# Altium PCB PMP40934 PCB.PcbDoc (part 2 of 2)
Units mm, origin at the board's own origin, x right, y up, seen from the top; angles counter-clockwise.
Board outline 30.1 x 65.43 mm, 4 copper layers (Component Side, Signal Layer 1, Signal Layer 2, Solder Side), stack 0.921 mm thick; 71 components, 34 nets, 202 pads, 421 vias.
Unrouted connection lines stored in the file: 46.
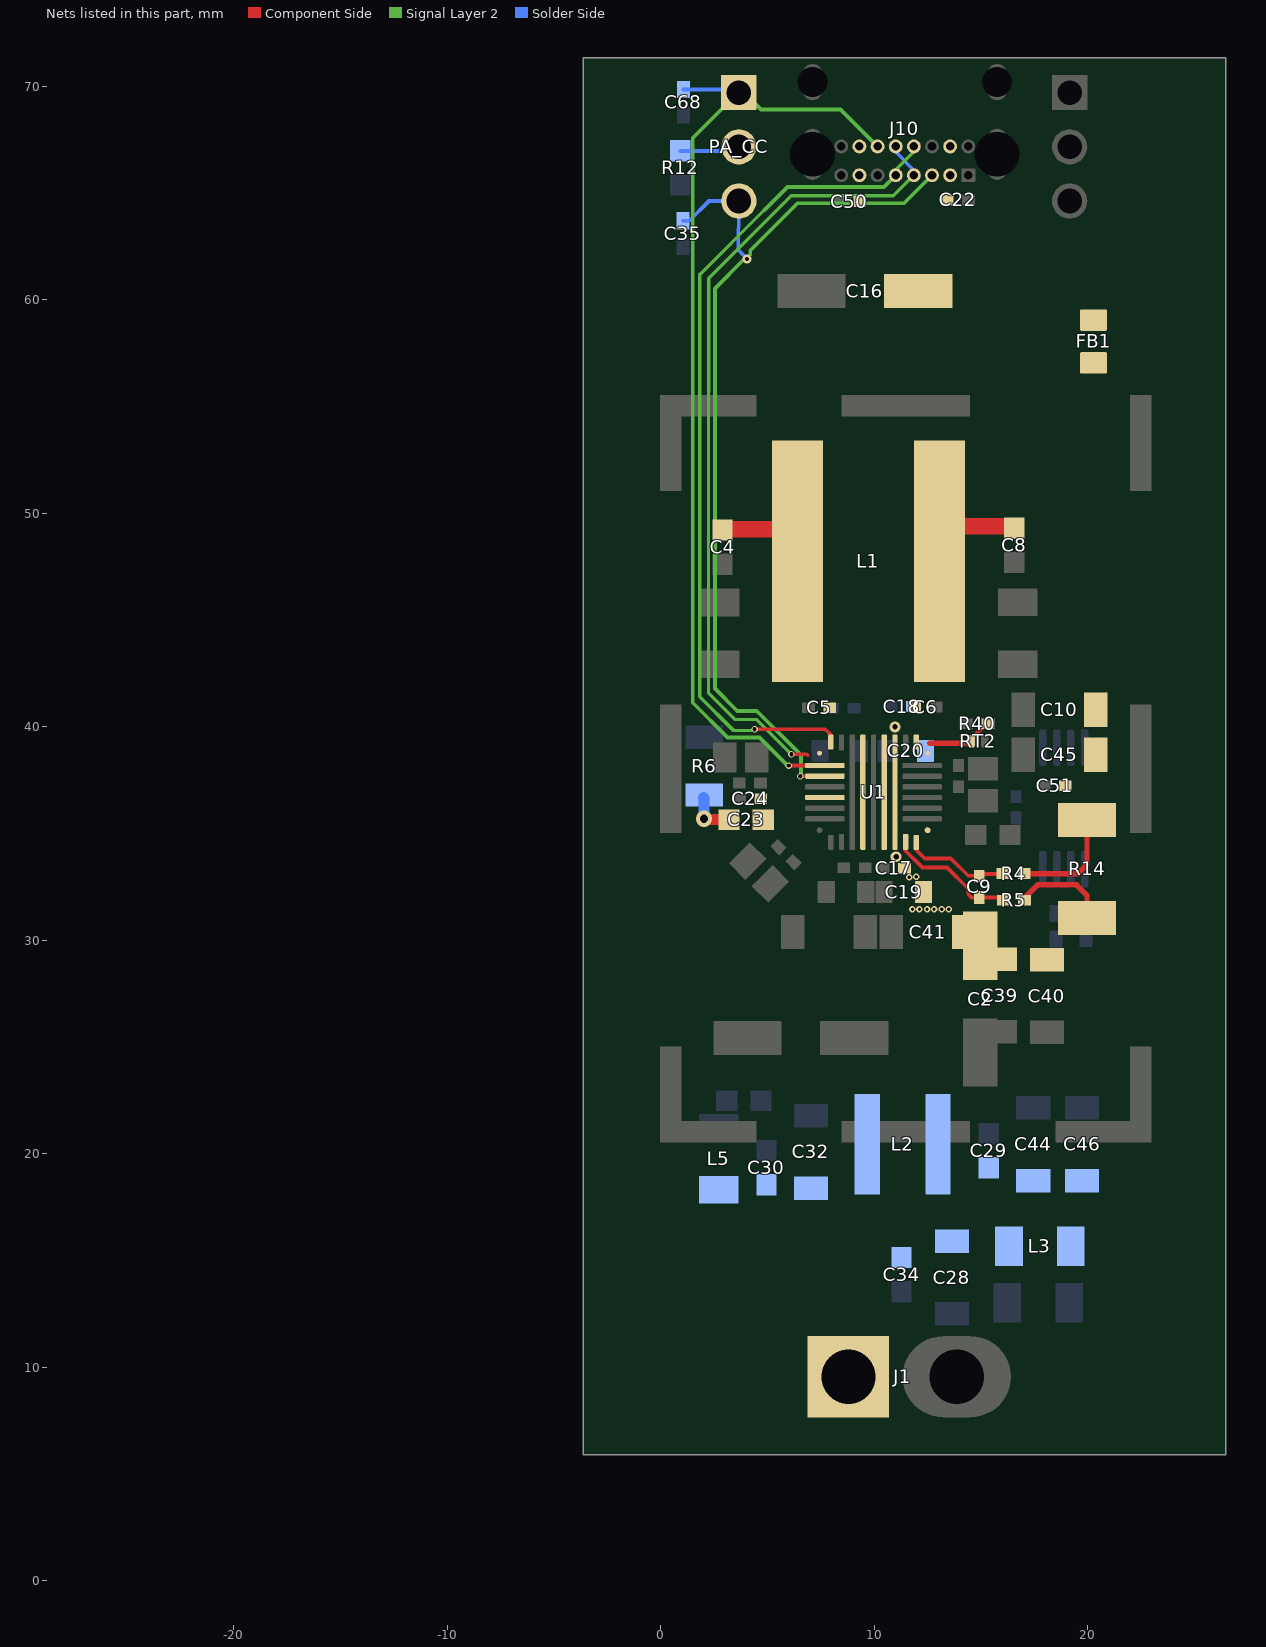
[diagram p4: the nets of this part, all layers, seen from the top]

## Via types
v1: diameter 0.762, hole 0.381, Component Side to Solder Side, 234 vias
v2: diameter 0.305, hole 0.152, Component Side to Solder Side, 135 vias
v3: diameter 0.305, hole 0.203, Component Side to Solder Side, 21 vias
v4: diameter 0.406, hole 0.203, Component Side to Solder Side, 10 vias
v5: diameter 0.381, hole 0.254, Component Side to Solder Side, tented both sides, 9 vias
v6: diameter 0.635, hole 0.381, Component Side to Solder Side, 7 vias
v7: diameter 0.508, hole 0.254, Component Side to Solder Side, 3 vias
v8: diameter 0.508/0.508/0.508/0.508 (per signal layer), hole 0.254, Component Side to Solder Side, 1 vias
v9: diameter 0.406, hole 0.254, Component Side to Solder Side, 1 vias

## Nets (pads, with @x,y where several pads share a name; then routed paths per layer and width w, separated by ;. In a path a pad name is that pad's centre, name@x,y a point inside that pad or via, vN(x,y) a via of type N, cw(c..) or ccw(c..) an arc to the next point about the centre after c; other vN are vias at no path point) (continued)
NetC9_1: C9.1 R5.1 U1.28 | length 6
  Component Side w0.178: U1.28@11.468,34.607 11.468,34.193 12.26,33.401 13.411,33.401 14.402,32.41 14.402,32.156 14.554,32.004 14.859,32.004 C9.1@14.884,31.979 ; C9.1@14.91,31.995 15.859,31.995 R5.1@16.002,31.852
NetC9_2: C9.2 R4.1 U1.29 | length 4.9
  Component Side w0.178: U1.29@11.968,34.582 11.968,34.227 12.363,33.833 13.586,33.833 14.398,33.02 C9.2@14.859,33.02 ; C9.2@14.91,32.995 15.011,33.096 16.002,33.096 R4.1@16.027,33.122
NetC10_1: C10.1 C45.1 C51.2 FB1.1 R4.2 R14.1 | length 5.2
  Component Side w0.254: R4.2@17.027,33.122 19.533,33.122 19.964,33.553 R14.1@19.964,35.636
NetC23_2: C23.2 R6.2 | length 2.4
  Component Side w0.508: v1@1.981,35.662 C23.2@3.429,35.662
  Solder Side w0.508: R6.2@2.007,36.678 2.032,36.652 v1(2.032,35.687)
NetC29_1: C29.1 C44.1 C46.1 L2.1 L3.2
NetC30_1: C30.1 C32.1 L2.2 L5.1
NetPA_CC_2: PA_CC.2 R12.2 | length 3
  Solder Side w0.178: R12.2@0.914,66.967 3.721,66.967 PA_CC.2@3.861,67.107
NTC: R40.1 RT2.2 U1.8 | length 3.1
  Component Side w0.178: RT2.2@14.554,39.446 15.24,40.132 R40.1@15.334,40.132
  Component Side w0.254: 12.593,39.219 12.594,39.218 14.529,39.218 RT2.2@14.58,39.268
OUT: C2.1 C17.2 C18.2 C19.2 C20.2 C39.1 C40.1 C41.1 R5.2 R14.2 U1.11 | length 4.5
  Component Side w0.254: R5.2@17.043,31.877 17.043,31.979 17.653,32.588 19.482,32.588 19.964,32.106 R14.2@19.964,31.036
  other v2: 11.786,31.445 12.116,31.445 12.471,31.445 12.802,31.445 13.157,31.445 13.487,31.445 11.633,32.944 11.963,32.969
  other v7: 11.024,33.909 10.973,39.992
PA_CC1: C35.1 J10.A5 PA_CC.3 U1.20 | length 44.4
  Component Side w0.178: v3(6.528,37.682) U1.20@7.693,37.682
  Signal Layer 2 w0.178: v4@4.013,61.9 3.912,61.9 2.54,60.528 2.54,41.783 3.581,40.742 4.47,40.742 ; v4@4.013,61.925 4.191,62.103 4.191,62.306 6.401,64.516 11.396,64.516 J10.A5@12.705,65.825 ; v3(6.528,37.682) 6.563,37.717 6.563,38.675 4.496,40.742 ; 4.47,40.742 4.496,40.742 ; 4.47,40.742 4.496,40.716 4.496,40.742
  Solder Side w0.178: C35.1@1.041,63.694 1.337,63.694 2.261,64.618 PA_CC.3@3.658,64.618 PA_CC.3@3.683,64.618 ; PA_CC.3@3.658,64.389 3.632,62.332 v4(4.039,61.9)
PA_CC2: C68.1 J10.B5 PA_CC.1 U1.19 | length 46.3
  Component Side w0.178: v3(6,38.182) U1.19@7.693,38.182
  Signal Layer 2 w0.178: PA_CC.1@3.581,69.647 1.499,67.564 1.499,41.123 3.124,39.497 4.623,39.497 5.938,38.182 v3(6,38.182) ; PA_CC.1@4.191,69.418 4.699,68.91 8.42,68.91 J10.B5@10.155,67.175
  Solder Side w0.178: C68.1@1.067,69.84 3.591,69.84 PA_CC.1@3.632,69.799
PA_D_N: J10.A7 J10.B7 U1.17 | length 40
  Component Side w0.152: v3(4.394,39.883) v3@4.399,39.878 ; U1.17@7.968,39.282 U1.17@7.968,39.618
  Component Side w0.178: v3@4.399,39.878 7.708,39.878 U1.17@7.968,39.618
  Signal Layer 2 w0.152: 1.829,41.402 1.829,55.842 ; 1.829,61.172 4.86,64.203 ; 3.391,39.84 3.37,39.819 v3@4.437,39.819 ; J10.A7@10.897,65.786 10.897,65.964 11.855,66.922 J10.B7@11.855,67.175
  Signal Layer 2 w0.178: 1.829,41.402 3.391,39.84 ; 1.829,55.842 1.829,61.172 ; 4.86,64.203 5.935,65.278 10.458,65.278 J10.A7@11.005,65.825
PA_D_P: J10.A6 J10.B6 U1.18 | length 38.8
  Component Side w0.152: v3@6.045,38.71 v3(6.121,38.71) ; 6.833,38.71 6.883,38.659
  Component Side w0.178: v3(6.121,38.71) 6.833,38.71
  Signal Layer 2 w0.152: v3(6.121,38.71) 4.496,40.335 3.488,40.335 2.235,41.588 2.235,55.656 2.248,55.668 2.248,60.998 6.109,64.859 10.889,64.859 J10.A6@11.855,65.825
  Signal Layer 2 w0.178: v3@6.112,38.776 6.121,38.766 v3(6.121,38.71)
  Solder Side w0.152: J10.B6@11.005,67.175 11.005,66.922 11.836,66.091 J10.A6@11.836,65.786
PA_VBUS: C16.1 C22.2 C50.2 FB1.2 J10.A4 J10.A9 J10.B4 J10.B9
PB_VBUS: U1.9
SW1: C4.1 C5.2 L1.1 U1.14 | length 4.7
  Component Side w0.762: C4.1@2.997,49.251 6.045,49.251 6.403,48.893 L1.1@6.403,47.752
SW2: C6.2 C8.1 L1.2 U1.12 | length 3.4
  Component Side w0.178: L1.2@13.183,49.403 L1.2@13.195,49.39
  Component Side w0.762: L1.2@13.195,49.39 C8.1@16.535,49.39 ; L1.2@13.208,49.555 L1.2@13.231,49.532
SYNC: U1.1
TVSP: C23.1 C24.1 U1.22 | length 0.1
  Component Side w0.178: C24.1@4.648,36.601 C24.1@4.728,36.682
VBAT: C28.1 C34.1 J1.1 L3.1
pads on no net: J10.A8 J10.B8 RT2.1S RT2.2S U1.23 U1.24 U1.25 U1.26

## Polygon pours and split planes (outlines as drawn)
AGND on Solder Side "Solder Side-AGND" (solid, pour order 1050): -6.909,73.05 -6.502,72.644 27.254,72.644 27.254,17.755 26.975,17.475 26.772,17.678 -4.242,17.678 -4.242,70.714 -6.096,72.568
no net on Solder Side "Solder Side-No Net 5" (solid, pour order 1048): 7.696,32.258
no net on Solder Side "Solder Side-No Net 6" (solid, pour order 1046): 7.874,32.182
no net on Solder Side "Solder Side-No Net 7" (solid, pour order 1044): 5.69,31.75
OUT on Solder Side "Solder Side-OUT 1" (solid, pour order 1042): 11.252,34.011 10.82,34.011 10.82,33.96 10.795,33.934 10.795,33.553 11.608,32.741 11.608,31.191 13.538,31.191 13.64,31.293 13.64,31.674 13.589,31.674
IN on Solder Side "Solder Side-IN 1" (solid, pour order 1040): 5.588,31.572 5.766,31.394 6.985,31.394 7.188,31.598 7.188,32.283 8.534,33.63 9.017,33.63 9.093,33.706 9.068,33.731 9.068,34.138 7.671,34.138 5.588,32.055
IN on Solder Side "Solder Side-IN" (solid, pour order 1004): 1.524,19.914 1.524,24.587 6.223,24.587 6.223,22.962 3.759,22.962 3.759,19.914
OUT on Solder Side "Solder Side-OUT" (solid, pour order 936): 12.175,39.734 12.776,39.133 12.776,38.532 12.751,38.532 12.484,38.291 12.421,38.227 12.04,38.227 11.938,38.329 11.938,39.084 11.408,39.631 ccw(c11.329,39.468) 11.329,39.649 10.973,39.649 10.744,39.878 10.744,40.183 10.846,40.284 10.909,40.297 10.922,40.31 11.227,40.31 11.227,40.361 11.506,40.64 11.506,41.173 11.582,41.25 12.04,41.25 12.141,41.148 12.141,40.589 11.734,40.182
AGND on Solder Side "Solder Side-GND 1" (solid, pour order 830): 8.69,41.986 8.69,40.861 8.708,40.843 9.298,40.843 9.677,40.464 9.677,39.776 10.262,39.776 10.262,40.471 10.516,40.725 11.032,40.725 11.125,40.818 11.125,41.986
AGND on Solder Side "SOLDER_SIDE_AGND_P1032" (solid, pour order 1032): 18.186,14.122 20.65,14.122 21.311,14.783 21.311,18.212 22.657,18.212 22.657,12.827 22.022,12.192 18.212,12.192
no net on Solder Side "Solder Side-No Net 4" (solid, pour order 1022): 0.991,70.739
BATGND on Solder Side "Solder Side-BATGND" (solid, pour order 1014): 17.221,14.3 17.196,11.608 17.165,6.786 11.301,6.814 11.359,12.632 10.82,12.878 10.846,14.3
no net on Solder Side "Solder Side-No Net 2" (solid, pour order 1012): 17.501,14.275
no net on Solder Side "Solder Side-No Net 3" (solid, pour order 1010): 17.247,14.275
VBAT on Solder Side "Solder Side-VBAT" (solid, pour order 1008): 11.049,16.475 11.268,16.498 16.989,16.475 16.967,14.554 10.389,14.478 10.389,12.573 10.827,12.379 10.77,6.74 6.426,6.731 6.454,14.279 9.906,16.475
IN on Solder Side "Solder Side-NetC1_2" (solid, pour order 934): 9.195,39.878 9.119,39.802 8.433,39.802 8.028,39.395 ccw(c8.119,39.378) 8.026,39.373 ccw(c8.252,39.359) 8.026,39.345 8.026,38.176 7.163,38.176 7.087,38.252 7.087,39.334 cw(c7.296,39.334) 7.148,39.482 7.276,39.61 cw(c7.677,39.21) 7.442,39.725 7.988,40.272 7.696,40.564 7.696,41.173 7.747,41.224 8.28,41.224 8.407,41.097 8.407,40.615 8.712,40.31 9.068,40.31 9.195,40.183
no net on Solder Side "Solder Side-No Net" (solid, pour order 938): 11.354,39.929
VBAT on Solder Side "SOLDER_SIDE_VBAT_P548" (solid, pour order 548): -4.706,23.968
SW1 on Solder Side "SOLDER_SIDE_SW1_P662" (solid, remove dead copper, pour order 662): 2.975,52.25
no net on Solder Side "Solder Side-No Net 1" (solid, pour order 886): 6.807,24.308
AGND on Component Side "COMPONENT_SIDE_AGND_P1024" (solid, pour order 1024): -7.53,17.526 27.889,17.526 27.889,70.764 -7.656,70.764
NetC10_1 on Component Side "Component Side-PA_VBUS" (solid, pour order 910): 18.491,34.112 18.517,34.087 21.539,34.087 21.539,57.429 18.58,57.429
SW2 on Component Side "Component Side-SW2" (solid, pour order 992): 12.189,41.148 12.192,41.148 13.157,42.113 13.945,42.113 14.199,42.367 14.203,42.62 ccw(c13.594,42.77) 14.205,42.631 14.205,53.885 ccw(c14.103,53.885) 14.103,53.987 11.665,53.987 ccw(c11.665,53.834) 11.513,53.834 10.573,41.481 10.378,40.65 10.344,40.347 10.319,34.276 ccw(c10.344,34.276) 10.344,34.251 10.471,34.251 ccw(c10.471,34.352) 10.573,34.352 10.573,40.194 cw(c10.827,40.194) 10.827,40.448 10.954,40.448 ccw(c10.954,40.982) 11.105,40.47 11.326,40.691 12.065,40.691 12.192,40.818
IN on Component Side "Component Side-IN" (solid, pour order 808): 8.738,34.138 7.722,33.35 7.188,33.35 6.985,33.35 4.191,30.556 3.505,30.556 1.981,29.032 1.981,23.554 ccw(c2.675,23.554) 2.184,23.063 ccw(c2.675,23.554) 2.675,22.86 4.982,22.86 ccw(c4.982,24.508) 5.055,22.862 5.586,22.86 ccw(c5.586,23.495) 6.221,23.495 ccw(c5.983,23.525) 6.223,23.527 6.223,27.508 6.223,28.169 7.105,28.992 cw(c7.643,27.841) 7.137,29.006 ccw(c7.137,30.314) 8.445,30.314 8.432,30.761 ccw(c8.079,30.782) 8.433,30.785 8.433,32.588 cw(c9.195,32.588) 8.669,33.139 8.951,33.422 ccw(c8.362,34.01) 9.195,34.011 ccw(c8.77,34.019) 9.195,34.026 9.195,40.234 ccw(c9.144,40.234) 9.144,40.284 8.814,40.284 ccw(c8.813,40.209) 8.738,40.208
SW1 on Component Side "Component Side-SW1" (solid, pour order 984): 8.839,40.437 8.738,40.437 8.509,40.657 7.823,40.665 7.798,40.64 7.645,40.792 7.645,41.127 7.241,41.531 6.647,42.121 6.325,42.121 5.461,42.139 5.008,42.591 5.008,42.741 cw(c5.384,42.799) 5.004,42.799 5.004,53.797 cw(c5.232,53.797) 5.232,54.026 5.258,54 7.701,54 cw(c7.701,53.828) 7.823,53.949 cw(c7.763,53.888) 7.849,53.888 9.383,41.08 ccw(c10.973,41.27) 9.483,40.683 cw(c7.902,40.06) 9.601,40.084 9.601,34.301 cw(c9.516,34.3) 9.576,34.239 9.347,34.239 cw(c9.347,34.265) 9.322,34.265 9.322,40.098 ccw(c7.747,39.083) 9.149,40.326 ccw(c7.876,39.201) 9.042,40.436 8.84,40.436
OUT on Component Side "Component Side-OUT" (solid, pour order 818): 12.211,33.09 12.884,33.09 14.656,31.32 17.716,31.331 18.136,31.75 18.136,32.156 18.517,32.156 21.514,32.156 21.514,28.702 20.98,28.169 14.249,28.169 11.608,30.81 11.582,31.699 11.582,32.415 ccw(c10.92,32.415) 11.388,32.884 11.131,33.141 cw(c12.048,34.057) 10.752,34.057 10.752,40.31 11.1,40.31 11.201,40.208 11.201,34.148 ccw(c11.326,34.148) 11.238,34.06 11.702,33.596
TVSP on Component Side "Component Side-TVSP" (solid, pour order 1034): 4.496,36.805 4.343,36.652 4.343,35.23 4.445,35.128 5.182,35.128 5.258,35.204 5.258,36.449 5.385,36.576 6.591,36.563 6.604,36.576 8.56,36.576 8.56,36.754 8.534,36.779 8.585,36.754 8.509,36.83 4.496,36.83
AGND on Component Side "Component Side-GND" (solid, pour order 828): 9.754,40.516 9.754,33.579 cw(c8.546,33.578) 9.751,33.495 cw(c8.954,33.588) 9.047,32.791 ccw(c9.121,32.569) 8.89,32.533 8.89,28.778 9.119,28.55 11.049,28.55 11.308,28.809 11.308,32.411 ccw(c10.928,32.411) 10.928,32.791 10.887,32.791 cw(c10.887,33.217) 10.604,32.899 cw(c11.432,33.831) 10.211,33.582 10.211,40.437 10.132,40.516
PA_VBUS on Component Side "Component Side-PA_VBUS 1" (solid, pour order 926): 8.866,61.724 8.866,61.213 11.836,58.242 21.438,58.242 21.438,59.665 21.412,59.741 20.422,60.731 15.57,60.731 14.745,61.557 13.767,62.535 13.741,62.56 13.741,67.412 13.614,67.539 13.386,67.539 13.183,67.335 13.183,65.176 12.827,64.821 9.982,64.821 9.677,65.126 9.677,67.412 9.423,67.666 9.093,67.666 8.865,67.437 8.865,61.776 ccw(c10.163,61.776)
no net on Component Side "Component Side-No Net 5" (solid, pour order 980): 18.948,10.973
no net on Component Side "Component Side-No Net 4" (solid, pour order 940): 10.338,39.497
no net on Component Side "Component Side-No Net 2" (solid, pour order 912): 19.761,56.363
no net on Component Side "Component Side-No Net 3" (solid, pour order 908): 3.581,32.817
OUT on Component Side "COMPONENT_SIDE_OUT_P644" (solid, remove dead copper, pour order 644): 13.803,43.081
OUT on Component Side "COMPONENT_SIDE_OUT_P646" (solid, remove dead copper, pour order 646): 14.087,43.081
SW1 on Component Side "Component Side-SW1 1" (solid, pour order 708): 13.868,43.073
AGND on Component Side "Component Side-GND 1" (solid, pour order 722): 13.284,37.998
no net on Component Side "Component Side-No Net 1" (solid, pour order 736): -21.819,52.845
OUT on Component Side "Component Side-OUT 1" (solid, pour order 770): 15.138,48.844
VBAT on Component Side "Component Side-NetC28_1 1" (solid, pour order 812): 11.836,53.797
VBAT on Component Side "Component Side-NetC28_1" (solid, pour order 814): 11.887,53.797
AGND on Signal Layer 2 "SIGNAL_LAYER_2_AGND_P1028" (solid, pour order 1028): -7.722,17.679 -7.722,71.603 30.48,71.603 30.48,17.679
no net on Signal Layer 2 "Signal Layer 2-No Net" (solid, pour order 1016): 14.732,40.64
OUT on Bottom Solder (solid): 13.627,31.305 13.614,31.318 13.614,31.75 11.151,34.214 10.897,34.214 10.795,34.112 10.795,33.782 11.506,33.071 11.506,32.868 11.659,32.715 11.659,31.369 11.786,31.242 13.564,31.242
IN on Bottom Solder (solid): 9.144,34.112 9.068,34.188 8.636,34.188 8.052,33.604 7.163,33.604 5.715,32.156 5.715,31.648 5.893,31.471 6.96,31.471 7.239,31.75 7.239,32.309 8.585,33.655 8.992,33.655 9.144,33.807
AGND on Signal Layer 1 "SIGNAL_LAYER_1_AGND_P1026" (solid, pour order 1026): -6.858,17.526 27.889,17.526 27.889,70.79 -6.858,70.79

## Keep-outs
Keep-Out Layer:
  the board outline again, w0.178
  text ".Layer_Name" at -14.91,-12.281 h1.52

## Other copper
Component Side:
  pour cut-out: 12.649,41.275 14.605,41.935 14.63,40.589 12.649,40.589
  pour cut-out: 15.443,48.717 17.755,48.717 17.755,43.586 15.443,43.586
  pour cut-out: 14.503,48.12 14.503,42.304 15.748,42.304 15.748,48.12
  pour cut-out: 14.18,31.621 14.727,31.621 17.081,31.534 17.081,31.432 14.241,31.511
  pour cut-out: 3.988,48.692 3.988,42.24 5.232,42.24 5.232,48.692
  pour cut-out: 1.905,33.096
  pour cut-out: 1.803,34.239
  pour cut-out: 18.594,58.268 21.59,58.268 21.59,57.48 18.591,57.48
  pour cut-out: 1.676,48.743 3.988,48.743 3.988,43.612 1.676,43.612
  pour cut-out: 5.131,41.986 6.35,41.986 7.087,41.377 7.112,40.03 5.131,40.03
  pour cut-out: 20.193,34.011 21.717,34.011 21.717,32.163 20.041,32.182 19.583,32.791 19.583,33.68
  pour cut-out: 18.339,33.96 18.872,33.96 18.974,34.112 19.66,34.087 19.787,34.087 19.787,33.63 19.507,33.35 18.339,33.35
  pour cut-out: 17.932,33.63 18.009,33.63 18.339,33.96 18.542,33.96 18.542,33.604 18.237,33.299 17.932,33.299
  region: 11.354,27.584
  region: 10.922,27.788
  region: 13.132,32.487
  region net SW2: 15.176,48.933
  region net OUT: 18.364,41.758
  region net OUT: 16.923,39.954
  region net OUT: 16.923,39.954
  region net OUT: 16.847,39.599
  region: 24.188,60.808
  pour cut-out: 7.987,54.077 11.363,54.077 10.566,43.637 9.195,43.637
  pour cut-out: -27.203,38.875
  pour cut-out: -25.121,33.331
  pour cut-out: -24.833,33.452
  pour cut-out: -13.277,48.301
  pour cut-out: 16.753,33.553
  pour cut-out: -22.174,33.885
Signal Layer 1:
  pour cut-out: 0.025,20.083
  pour cut-out: 2.126,23.724
Signal Layer 2:
  pour cut-out: 8.814,68.377 8.814,66.015 14.046,66.015 14.097,66.065 14.097,68.428
Solder Side:
  rectangle net NetC29_1: 18.161,14.757 20.726,19.253
  rectangle net NetC29_1: 11.887,17.831 20.777,19.888
  rectangle net NetC29_1: 11.887,17.831 14.122,22.936
  rectangle net NetC30_1: 8.763,17.856 10.82,22.936
  rectangle net NetC30_1: 1.549,17.704 10.795,19.38
  pour cut-out: 17.043,36.17 17.297,36.17 17.297,35.585 17.247,35.535 17.043,35.535
  pour cut-out: 10.82,23.089 11.862,23.089 11.836,17.45 10.846,17.424
  pour cut-out: 17.628,34.95 18.085,34.493 19.939,34.493 19.939,34.874 18.974,35.839 17.907,35.839 17.602,35.535 17.628,35.509
  pour cut-out: 5.055,54.458
  pour cut-out: 9.026,0.838
  pour cut-out: 16.273,24.757

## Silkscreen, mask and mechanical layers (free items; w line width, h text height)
Top Overlay:
  lines w0.025: 5.131,42.088 7.874,42.088 ; 12.014,42.113 14.021,42.113
  text "GND" at 21.463,69.444 h0.51
  text "SCL" at 21.438,66.954 h0.51
  text "SDA" at 21.412,64.414 h0.51
  text "TPS25762 Single EMCE" at 20.904,43.053 h1.27 r90
  text "PMP40934 E3" at 3.835,13.386 h2.54
  text "Vbat" at 1.854,8.23 h1.52
  text "GND" at 18.39,8.052 h1.52
  text ".Layer_Name" at -14.91,-12.281 h1.52
Bottom Overlay:
  text ".Layer_Name" at -14.91,-12.281 h0.51
Top Paste:
  text ".Layer_Name" at -14.91,-12.281 h1.52
Bottom Paste:
  text ".Layer_Name" at -14.91,-12.281 h1.52
Top Solder:
  text ".Layer_Name" at -14.91,-12.281 h1.52
  text ".Layer_Name" at -14.91,-12.281 h1.52
Bottom Solder:
  text ".Layer_Name" at -14.91,-12.281 h1.52
Drill Guide:
  text ".Layer_Name" at -14.91,-12.281 h1.52
M1 Board Outline:
  text ".Layer_Name" at -14.91,-12.281 h1.52
M2 Board Dimensions:
  rectangle: -32.487,1.346 -22.962,4.521
  rectangle: -35.662,4.521 -32.487,7.696
  lines w0.178: -35.662,4.521 -10.262,4.521 ; -32.487,1.346 -32.487,7.696 ; -29.312,1.346 -29.312,7.696 ; -22.962,1.346 -22.962,7.696 ; -16.612,1.346 -16.612,7.696 ; -35.662,1.346 -35.662,7.696 -10.262,7.696 -10.262,1.346 -35.662,1.346
  text ".Layer_Name" at -14.91,-12.281 h1.52
M3 3D STEP Top:
  text ".Layer_Name" at -14.91,-12.281 h1.52
M4 3D STEP Bottom:
  text ".Layer_Name" at -14.91,-12.281 h1.52
M5 Assembly Top:
  lines w0.254: -36.982,-14.101 130.658,-14.101 ; -36.982,-8.937 130.708,-8.937 ; -36.982,-3.772 -36.982,-19.266 64.745,-19.266 ; 3.048,-19.266 -36.97,-19.266 -36.97,-3.772 130.708,-3.772 130.708,-19.266 ; 25.629,-19.266 25.629,-3.772 ; 57.81,-8.937 57.81,-3.772 ; 79.146,-8.937 79.146,-3.772 ; 94.945,-19.431 94.945,-14.279
  text "COMPONENTS MARKED 'DNP' SHOULD NOT BE POPULATED." at -0.267,1.435 h1.52
  text "ASSEMBLY VARIANT:" at -0.279,-1.499 h1.52
  text ".VariantName" at 26.035,-1.499 h1.52
  text "PCB VIEWED FROM TOP SIDE" at -35.369,-7.129 h1.52
  text "BOARD #:" at 27.534,-7.129 h1.52
  text ".PRJ_Number" at 41.389,-7.129 h1.52
  text "REV:" at 62.84,-7.129 h1.52
  text ".PCB_Rev" at 70.244,-7.129 h1.52
  text "SVN REV:" at 84.125,-7.129 h1.52
  text ".VersionControl_RevNumber" at 96.977,-7.129 h1.52
  text "TID #:" at 27.534,-12.294 h1.52
  text ".TID" at 41.389,-12.294 h1.52
  text "PLOT NAME =" at -35.369,-17.509 h1.52
  text ".plot_File_Name" at -14.91,-17.509 h1.52
  text "GENERATED    :" at 27.584,-17.509 h1.52
  text ".Print_Date" at 49.67,-17.509 h1.52
  text ".Print_Time" at 68.186,-17.509 h1.52
  text "TEXAS INSTRUMENTS" at 100.305,-17.509 h1.52
M6 Assembly Bottom:
  lines w0.254: -36.995,-8.949 130.696,-8.949 ; -36.944,-14.114 130.696,-14.114 ; -1.232,-19.444 -1.232,-14.292 ; 14.567,-8.949 14.567,-3.785 ; 28.969,-19.279 -36.995,-19.279 -36.995,-3.785 130.683,-3.785 130.683,-19.279 ; 35.903,-8.949 35.903,-3.785 ; 68.085,-19.279 68.085,-3.785 ; 130.696,-19.279 130.696,-3.785
  text "COMPONENTS MARKED 'DNP' SHOULD NOT BE POPULATED." at 125.425,1.448 h1.52
  text ".VariantName" at 98.908,-1.499 h1.52
  text "ASSEMBLY VARIANT:" at 125.298,-1.499 h1.52
  text ".VersionControl_RevNumber" at -3.264,-7.142 h1.52
  text "SVN REV:" at 9.588,-7.142 h1.52
  text ".PCB_Rev" at 23.47,-7.142 h1.52
  text "REV:" at 30.874,-7.142 h1.52
  text ".PRJ_Number" at 52.324,-7.142 h1.52
  text "BOARD #:" at 66.18,-7.142 h1.52
  text "PCB VIEWED FROM BOTTOM SIDE" at 129.083,-7.142 h1.52
  text ".TID" at 52.324,-12.306 h1.52
  text "TID #:" at 66.18,-12.306 h1.52
  text "TEXAS INSTRUMENTS" at -6.591,-17.522 h1.52
  text ".Print_Time" at 25.527,-17.522 h1.52
  text ".Print_Date" at 44.044,-17.522 h1.52
  text "GENERATED    :" at 66.129,-17.522 h1.52
  text ".plot_File_Name" at 108.623,-17.522 h1.52
  text "PLOT NAME =" at 129.083,-17.522 h1.52
M9 Title Sheet:
  drawing of 51 lines, arcs and shapes, not listed
  text "1" at -10.774,213.652 h1.78
  text "2" at 52.616,213.652 h1.78
  text "A" at -40.145,184.62 h1.78
  text "B" at -40.145,124.168 h1.78
  text "B" at 335.775,124.168 h1.78
  text "C" at -40.145,63.843 h1.78
  text "C" at 335.775,63.843 h1.78
  text "PROJECT TITLE:" at 258.559,16.573 h1.14
  text ".PRJ_Title" at 259.829,13.187 h1.78
  text "DESIGNED FOR:" at 258.559,8.928 h1.14
  text ".PRJ_Customer" at 259.829,5.372 h1.78
  text "D" at -40.145,3.645 h1.78
  text "D" at 335.775,3.645 h1.78
  text "FILE NAME:" at 258.559,1.308 h1.14
  text ".PCB_File_Name_No_Path" at 259.829,-1.74 h1.78
  text "Texas Instruments (TI) and/or its licensors do not warrant the accuracy or completeness of this specification" at 132.334,-5.851 h1.14
  text "ENGINEER:" at 258.559,-6.058 h1.14
  text "LAYOUT BY:" at 296.786,-6.058 h1.14
  text "or any information contained therein. TI and/or its licensors do not warrant that this design will meet" at 131.191,-8.712 h1.14
  text ".PRJ_Engineer" at 259.829,-9.995 h1.78
  text ".PCB_Layout" at 298.069,-9.995 h1.78
  text "the specifications, will be suitable for your application or fit for any particular purpose, or will operate in" at 131.191,-11.574 h1.14
  text ".Layer_Name" at -14.91,-12.281 h1.52
  text "ALTIUM DESIGNER VERSION:" at 296.786,-13.932 h1.14
  text "an implementation. TI and/or its licensors do not warrant that the design is production worthy. You should" at 131.191,-14.436 h1.14
  text "completely validate and test your design implementation to confirm the system functionality for your application." at 132.334,-17.297 h1.14
  text ".print_Scale" at 259.829,-17.318 h1.78
  text ".Application_BuildNumber" at 298.069,-17.318 h1.78
  text "5" at 242.989,-22.568 h1.78
  text "6" at 306.616,-22.568 h1.78
M10 Fab Notes:
  drawing of 189 lines, arcs and shapes, not listed
  text "HOLE SIZE TOLERANCE (UNLESS OTHERWISE SPECIFIED):" at 7.954,256.176 h1.52
  text "+/-" at 68.146,256.103 h1.52
  text "3" at 74.222,256.076 h1.52
  text "MIL" at 77.175,256.076 h1.52
  text "MATERIAL:" at 6.055,252.58 h1.52
  text "FR-4 High Tg" at 31.11,249.315 h1.52
  text "X" at 27.442,249.113 h1.52
  text "FR-408" at 16.748,248.998 h1.52
  text "OTHER" at 54.543,248.998 h1.52
  text "62 MIL (1.6mm) +/-10%" at 24.629,247.415 h1.52
  text "X" at 21.579,247.353 h1.52
  text "THICKNESS:" at 7.704,247.207 h1.52
  text "OTHER" at 57.266,247.207 h1.52
  text "DESIGN INFORMATION" at 284.925,170.972 h1.52
  text "MIN. TRACK WIDTH:" at 268.553,167.616 h1.52
  text "8" at 296.398,167.616 h1.52
  text "MIL" at 300.329,167.616 h1.52
  text "MIN. CLEARANCE:" at 268.553,164.463 h1.52
  text "0.2" at 294.874,164.463 h1.52
  text "mm" at 300.329,164.463 h1.52
  text "MIN. VIA PAD SIZE:" at 268.553,161.31 h1.52
  text "24" at 295.636,161.31 h1.52
  text "MIL" at 300.329,161.31 h1.52
  text "0.05mm (2MIL)" at 286.219,158.011 h1.52
  text "MINIMUM ANNULAR RING" at 260.203,157.802 h1.52
  text "EXTERNAL" at 304.202,157.802 h1.52
  text "PER" at 265.533,151.979 h1.52
  text "IPC-D-275 CLASS 2 LEVEL C" at 271.121,151.979 h1.52
  text "MIL, HOLES" at 308.922,150.402 h1.52
  text "+/-" at 298.953,150.184 h1.52
  text "+/-" at 320.645,150.184 h1.52
  text "REGISTRATION TOLERANCES:" at 260.453,150.157 h1.52
  text "METAL" at 290.927,150.157 h1.52
  text "5" at 305.562,150.157 h1.52
  text "3" at 326.721,150.157 h1.52
  text "MIL" at 329.674,150.157 h1.52
  text "TOLERANCE:" at 260.203,135.177 h1.52
  text "X" at 281.749,135.177 h1.52
  text "ANSI IPC-6012 TYPE 3 CLASS 2" at 286.27,135.177 h1.52
  text "OTHER +/-" at 286.27,131.514 h1.52
  text "BOW & TWIST:" at 260.203,127.827 h1.52
  text "X" at 281.749,127.827 h1.52
  text "ANSI IPC-6012 TYPE 3 CLASS 2" at 286.27,127.827 h1.52
  text "OTHER +/-" at 286.27,124.101 h1.52
  text "DRILLING:" at 258.304,120.783 h1.52
  text "NC_DRILL FILES" at 303.034,118.111 h1.52
  text "REFERENCE:" at 260.203,118.011 h1.52
  text "X" at 276.897,118.009 h1.52
  text "AS SHOWN" at 281.418,118.011 h1.52
  text "X" at 299.783,118.011 h1.52
  text "OTHER" at 310.603,114.398 h1.52
  text "PTH COPPER THICKNESS:" at 260.195,114.308 h1.52
  text "X" at 289.132,114.308 h1.52
  text "20-30 um" at 292.383,114.308 h1.52
  text "BOARD FINISH:" at 258.304,110.559 h1.52
  text "SILKSCREEN:" at 262.247,107.762 h1.52
  text "X" at 286.575,107.762 h1.52
  text "TOP" at 289.546,107.762 h1.52
  text "X" at 299.529,107.762 h1.52
  text "BOTTOM" at 302.526,107.762 h1.52
  text "SILKSCREEN COLOR:" at 262.247,103.82 h1.52
  text "X" at 286.549,103.82 h1.52
  text "WHITE" at 289.546,103.82 h1.52
  text "OTHER" at 302.526,103.82 h1.52
  text "X" at 289.877,100.177 h1.52
  text "GREEN" at 292.874,100.177 h1.52
  text "OTHER" at 308.571,100.177 h1.52
  text "SOLDER RESIST COLOR:" at 262.247,100.002 h1.52
  text "X" at 289.877,96.259 h1.52
  text "MATTE" at 292.874,96.259 h1.52
  text "SEMI-GLOSS" at 308.559,96.242 h1.52
  text "IMMERSION GOLD (ENIG)" at 285.254,91.87 h1.52
  text "ENEPIG" at 319.227,91.687 h1.52
  text "SURFACE FINISH:" at 258.304,91.661 h1.52
  text "X" at 280.733,91.661 h1.52
  text "IMM. TIN/SILVER OR EQUIV" at 266.675,88.174 h1.52
  text "OTHER" at 303.034,88.074 h1.52
  text "ARRAY/PANEL:" at 258.304,84.127 h1.52
  text "CUT AND TRIM PER M1 BOARD OUTLINE" at 285.254,83.918 h1.52
  text "N.C. ROUTE" at 285.254,80.465 h1.52
  text "X" at 302.729,80.465 h1.52
  text "V. SCORE" at 307.25,80.465 h1.52
  text "CERTIFICATION:" at 258.304,77.185 h1.52
  text "MATERIALS AND WORKMANSHIP FOR ALL PCBS" at 276.719,77.185 h1.52
  text "TO MEET OR EXCEED THE REQUIREMENTS OF:" at 276.719,74.796 h1.52
  text "X" at 267.512,71.528 h1.52
  text "ANSI IPC-A-600F CLASS ->" at 270.763,71.528 h1.52
  text "X" at 312.622,71.528 h1.52
  text "2" at 315.416,71.528 h1.52
  text "1" at 307.415,71.49 h1.52
  text "3" at 324.408,71.49 h1.52
  text "X" at 288.137,67.777 h1.52
  text "RoHS" at 291.388,67.777 h1.52
  text "OTHER" at 307.756,67.777 h1.52
  text "PER ORDER" at 317.841,67.777 h1.52
  text "ALL BOARDS MUST MEET OR EXCEED UL94-V0 REQUIREMENTS." at 259.004,63.87 h1.52
  text "PCB MUST BEAR THE UL94V-0 UL REGISTERED MATERIAL ID NUMBER" at 259.004,60.922 h1.52
  text "ADDITIONAL REQUIREMENTS:" at 258.304,56.619 h1.52
  text "MICROSECTION:" at 260.203,53.898 h1.52
  text "YES" at 283.209,53.898 h1.52
  text "REQUIRED" at 305.091,50.232 h1.52
  text "BARE BOARD ELEC. TEST:" at 260.203,50.159 h1.52
  text "NONE" at 293.369,50.159 h1.52
  text "X" at 302.094,50.159 h1.52
  text "PER ORDER" at 320.128,50.159 h1.52
  text "XX MIL VIAS REQUIRE NON-CONDUCTIVE FILL AND PLANARIZE" at 264.474,44.953 h1.5
  text "XX MIL VIAS REQUIRE CONDUCTIVE FILL AND PLANARIZE" at 264.678,42.312 h1.52
  text "OUTER XX MIL TRACES REQUIRE 50 OHM SINGLE-ENDED IMPEDANCE" at 264.653,38.162 h1.47
  text "LAYER 2 & 3 (INNER LAYERS) XX MIL WIDE, XX MIL SPACE / TRACES REQUIRE 100 OHM DIFFERENTIAL IMPEDANCE" at 264.449,32.175 h1.52
  text ".Layer_Name" at -14.91,-12.281 h1.52
M11 Gerber Information:
  lines w0.254: -36.982,-14.101 130.658,-14.101 ; -36.982,-8.937 130.708,-8.937 ; -36.982,-3.772 -36.982,-19.266 64.745,-19.266 ; 3.048,-19.266 -36.97,-19.266 -36.97,-3.772 130.708,-3.772 130.708,-19.266 ; 25.629,-19.266 25.629,-3.772 ; 57.81,-8.937 57.81,-3.772 ; 79.146,-8.937 79.146,-3.772 ; 94.945,-19.431 94.945,-14.279
  text "ALL ARTWORK VIEWED FROM TOP SIDE" at -35.369,-7.129 h1.52
  text "BOARD #:" at 27.534,-7.129 h1.52
  text ".PRJ_Number" at 41.389,-7.129 h1.52
  text "REV:" at 62.84,-7.129 h1.52
  text ".PCB_Rev" at 70.244,-7.129 h1.52
  text "SVN REV:" at 84.125,-7.129 h1.52
  text ".VersionControl_RevNumber" at 96.977,-7.129 h1.52
  text "LAYER NAME =" at -35.369,-12.281 h1.52
  text "TID #:" at 27.534,-12.294 h1.52
  text ".TID" at 41.389,-12.294 h1.52
  text "PLOT NAME =" at -35.369,-17.509 h1.52
  text ".plot_File_Name" at -14.91,-17.509 h1.52
  text "GENERATED    :" at 27.584,-17.509 h1.52
  text ".Print_Date" at 49.67,-17.509 h1.52
  text ".Print_Time" at 68.186,-17.509 h1.52
  text "TEXAS INSTRUMENTS" at 100.305,-17.509 h1.52
M12 Stackup:
  drawing of 295 lines, arcs and shapes, not listed
  text "Layer" at 355.688,58.481 h1.52
  text "Name" at 366.1,58.481 h1.52
  text "Material" at 389.969,58.481 h1.52
  text "Thickness" at 411.807,58.481 h1.52
  text "Constant" at 428.313,58.481 h1.52
  text "Board Layer Stack" at 442.787,58.481 h1.52
  text "1" at 355.688,55.433 h1.52
  text "Top Overlay" at 366.1,55.433 h1.52
  text "2" at 355.688,52.385 h1.52
  text "Top Solder" at 366.1,52.385 h1.52
  text "Solder Resist" at 389.969,52.385 h1.52
  text "0.40mil" at 411.807,52.385 h1.52
  text "3.5" at 428.313,52.385 h1.52
  text "3" at 355.688,49.337 h1.52
  text "Component Side" at 366.1,49.337 h1.52
  text "Copper" at 389.969,49.337 h1.52
  text "2.84mil" at 411.807,49.337 h1.52
  text "4" at 355.688,46.289 h1.52
  text "Dielectric 1" at 366.1,46.289 h1.52
  text "FR-4" at 389.969,46.289 h1.52
  text "10.00mil" at 411.807,46.289 h1.52
  text "4.8" at 428.313,46.289 h1.52
  text "5" at 355.688,43.241 h1.52
  text "Signal Layer 1" at 366.1,43.241 h1.52
  text "Copper" at 389.969,43.241 h1.52
  text "2.80mil" at 411.807,43.241 h1.52
  text "6" at 355.688,40.193 h1.52
  text "Dielectric 3" at 366.1,40.193 h1.52
  text "5.00mil" at 411.807,40.193 h1.52
  text "4.2" at 428.313,40.193 h1.52
  text "7" at 355.688,37.145 h1.52
  text "Signal Layer 2" at 366.1,37.145 h1.52
  text "Copper" at 389.969,37.145 h1.52
  text "2.80mil" at 411.807,37.145 h1.52
  text "8" at 355.688,34.097 h1.52
  text "Dielectric 4" at 366.1,34.097 h1.52
  text "FR-4" at 389.969,34.097 h1.52
  text "10.00mil" at 411.807,34.097 h1.52
  text "4.8" at 428.313,34.097 h1.52
  text "9" at 355.688,31.049 h1.52
  text "Solder Side" at 366.1,31.049 h1.52
  text "Copper" at 389.969,31.049 h1.52
  text "2.84mil" at 411.807,31.049 h1.52
  text "10" at 355.688,28.001 h1.52
  text "Bottom Solder" at 366.1,28.001 h1.52
  text "Solder Resist" at 389.969,28.001 h1.52
  text "0.40mil" at 411.807,28.001 h1.52
  text "3.5" at 428.313,28.001 h1.52
  text "11" at 355.688,24.953 h1.52
  text "Bottom Overlay" at 366.1,24.953 h1.52
  text ".Layer_Name" at -14.91,-12.281 h1.52
M13 Component Bodies Top:
  text ".Layer_Name" at -14.91,-12.281 h1.52
M14 Component Bodies Bottom:
  text ".Layer_Name" at -14.91,-12.281 h1.52
M15 Courtyards Top:
  text ".Layer_Name" at -14.91,-12.281 h1.52
M16 Courtyards Bottom:
  text ".Layer_Name" at -14.91,-12.281 h1.52
Drill Drawing:
  circle w0.254: c106.673,120.589 r0.702
  lines w0.254: 105.971,99.187 107.375,99.187 106.673,97.783 105.971,99.187 ; 105.971,101.292 106.322,101.292 106.673,100.941 107.024,101.292 107.375,101.292 107.024,101.643 107.375,101.993 107.024,101.993 106.673,102.344 106.322,101.993 105.971,101.993 106.322,101.643 105.971,101.292 ; 105.971,104.099 105.971,104.449 106.322,104.8 105.971,105.151 105.971,105.502 106.322,105.502 106.673,105.151 107.024,105.502 107.375,105.502 107.375,105.151 107.024,104.8 107.375,104.449 107.375,104.099 107.024,104.099 106.673,104.449 106.322,104.099 105.971,104.099 ; 105.971,107.256 106.673,107.607 107.375,107.256 107.024,107.958 107.375,108.66 106.673,108.309 105.971,108.66 106.322,107.958 105.971,107.256 ; 105.971,110.765 106.322,110.765 106.673,110.414 107.024,110.765 107.375,110.765 107.024,111.116 107.375,111.467 107.024,111.467 106.673,111.817 106.322,111.467 105.971,111.467 106.322,111.116 105.971,110.765 ; 105.971,114.975 107.375,114.975 106.673,113.572 105.971,114.975 ; 105.971,116.729 107.375,116.729 107.375,118.133 105.971,118.133 105.971,116.729 ; 105.971,123.045 106.673,123.396 107.375,123.045 107.024,123.747 107.375,124.448 106.673,124.098 105.971,124.448 106.322,123.747 105.971,123.045 ; 106.252,98.906 107.094,98.906 106.673,98.064 106.252,98.906 ; 106.252,101.432 106.462,101.432 106.673,101.222 106.883,101.432 107.094,101.432 106.883,101.643 107.094,101.853 106.883,101.853 106.673,102.064 106.462,101.853 106.252,101.853 106.462,101.643 106.252,101.432 ; 106.252,107.537 106.673,107.748 107.094,107.537 106.883,107.958 107.094,108.379 106.673,108.169 106.252,108.379 106.462,107.958 106.252,107.537
  lines w0.305: 104.699,96.836 189.704,96.836 ; 104.699,125.255 189.704,125.255 ; 113.28,93.678 113.28,128.413 ; 121.713,93.678 121.713,128.413 ; 137.882,93.678 137.882,128.413 ; 144.464,93.678 144.464,128.413 ; 153.993,93.678 153.993,128.413 ; 175.316,93.678 175.316,128.413 ; 104.699,93.678 189.704,93.678 189.704,128.413 104.699,128.413 104.699,93.678
  text "Symbol" at 106.593,126.203 h1.83
  text "Quantity" at 114.228,126.203 h1.83
  text "Finished Hole Size" at 122.661,126.203 h1.83
  text "Plated" at 138.829,126.203 h1.83
  text "Hole Type" at 145.411,126.203 h1.83
  text "Drill Layer Pair" at 154.941,126.203 h1.83
  text "Hole Tolerance" at 176.264,126.203 h1.83
  text "135" at 114.228,123.045 h1.52
  text "6.00mil (0.152mm)" at 122.661,123.045 h1.52
  text "PTH" at 138.829,123.045 h1.52
  text "Round" at 145.411,123.045 h1.52
  text "Component Side - Solder Side" at 154.941,123.045 h1.52
  text "31" at 114.228,119.887 h1.52
  text "8.00mil (0.203mm)" at 122.661,119.887 h1.52
  text "PTH" at 138.829,119.887 h1.52
  text "Round" at 145.411,119.887 h1.52
  text "Component Side - Solder Side" at 154.941,119.887 h1.52
  text "14" at 114.228,116.729 h1.52
  text "10.00mil (0.254mm)" at 122.661,116.729 h1.52
  text "PTH" at 138.829,116.729 h1.52
  text "Round" at 145.411,116.729 h1.52
  text "Component Side - Solder Side" at 154.941,116.729 h1.52
  text "241" at 114.228,113.572 h1.52
  text "15.00mil (0.381mm)" at 122.661,113.572 h1.52
  text "PTH" at 138.829,113.572 h1.52
  text "Round" at 145.411,113.572 h1.52
  text "Component Side - Solder Side" at 154.941,113.572 h1.52
  text "16" at 114.228,110.414 h1.52
  text "15.75mil (0.400mm)" at 122.661,110.414 h1.52
  text "PTH" at 138.829,110.414 h1.52
  text "Round" at 145.411,110.414 h1.52
  text "Component Side - Solder Side" at 154.941,110.414 h1.52
  text "6" at 114.228,107.256 h1.52
  text "45.28mil (1.150mm)" at 122.661,107.256 h1.52
  text "PTH" at 138.829,107.256 h1.52
  text "Round" at 145.411,107.256 h1.52
  text "Component Side - Solder Side" at 154.941,107.256 h1.52
  text "2" at 114.228,104.099 h1.52
  text "100.00mil (2.540mm)" at 122.661,104.099 h1.52
  text "PTH" at 138.829,104.099 h1.52
  text "Round" at 145.411,104.099 h1.52
  text "Component Side - Solder Side" at 154.941,104.099 h1.52
  text "2" at 114.228,100.941 h1.52
  text "55.12mil (1.400mm)" at 122.661,100.941 h1.52
  text "PTH" at 138.829,100.941 h1.52
  text "Slot" at 145.411,100.941 h1.52
  text "Component Side - Solder Side" at 154.941,100.941 h1.52
  text "2" at 114.228,97.783 h1.52
  text "82.68mil (2.100mm)" at 122.661,97.783 h1.52
  text "PTH" at 138.829,97.783 h1.52
  text "Slot" at 145.411,97.783 h1.52
  text "Component Side - Solder Side" at 154.941,97.783 h1.52
  text "449 Total" at 114.228,94.625 h1.52
  text "Slot definitions :" at 106.593,92.415 h1.52
  text "Routed Path Length" at 118.042,92.415 h1.52
  text "= Calculated from tool start centre position to tool end centre position." at 131.751,92.415 h1.52
  text "Hole Length" at 118.042,91.152 h1.52
  text "= Routed Path Length + Tool Size = Slot length as defined in the PCB layout" at 126.676,91.152 h1.52
  text ".Layer_Name" at -14.91,-12.281 h1.52
M17 Embedded Cavity:
  text ".Layer_Name" at -14.91,-12.281 h1.52
M18 Embedded Assembly:
  text ".Layer_Name" at -14.91,-12.281 h1.52
M19 Embedded Keepout:
  text ".Layer_Name" at -14.91,-12.281 h1.52

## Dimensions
-3.632,5.893 to 26.467,5.893 on M2 Board Dimensions
-3.632,5.893 to -1.168,71.298 on M2 Board Dimensions
-35.662,1.346 to -10.262,1.346 on M2 Board Dimensions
